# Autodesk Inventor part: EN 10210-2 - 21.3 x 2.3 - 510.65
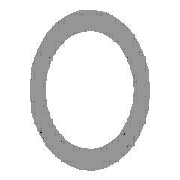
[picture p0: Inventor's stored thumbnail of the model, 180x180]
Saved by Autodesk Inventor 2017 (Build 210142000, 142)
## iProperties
Created: 2017-11
Part Number: EN 10210-2 - 21.3 x 2.3 - 510.65
Material: Steel, Mild
Description: Pipe
Document SubType Name: Modeling
Standard: DIN
Designer: iusti
Standard Revision: 2006-07
Standards Organization: DIN
Language: en-US
Size Designation: 21.3 x 2.3
Categories: <MemberInstance><Categories><Category DisplayName="Structural Shapes" InternalName="089c4875-fa83-4c05-b084-43b9cc11f5ed" Mnemonic="GRDR"><CategoryParameter Dis
Stock Number: 21.3 x 2.3
Density: 7.85 g/cm^3
Appearance: Semi-Polished
_CCFamilyMember: 1
_CCFamilyDisplayName: DIN EN 10210-2 - Pipe
_FrameMemberDoc: Frame Member File
_Version: 15.0.0
_GetPNFromCC: 1
G_L: 510.650 mm
G_W: 21.300 mm
G_H: 21.300 mm
+22488682-7980-44F7-8CC4-272C3B725D64+CUTDETAIL1: Miter 45.00 deg
IsCustomPart: 1
Author: iusti
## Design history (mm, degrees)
node "Start plane"
node "End plane"
sketch "Sketch"
  geometry: C1 r 8.35 at (0, 0); C2 r 10.65 at (0, 0); 2 further points
  constraints: 3 coincident, 2 centre point
  dimensions: "d0" = 21.3 diameter of C2 (= G_H); "d1" = 2.3 radial gap between concentric circles of C2 C1 (= G_T)
extrude "Body" new body sketch "Sketch" stored distance "d2" = 510.65 (= G_L); taper "d3" = 0 deg
node "Driven Length"
  sketch "Sketch3"
    geometry: L1 (0, 0)-(10, 0) reference
    constraints: 2 end point, 1 horizontal
  workplane "Work Plane3"
  sketch "Sketch4"
    geometry: L1 (-2, 0)-(12, 0) reference; L2 (-2, 510.65)-(12, 510.65) reference
    dimensions: "d7" = 510.65 distance between parallel lines of L1 L2 (derived)
workplane "Work Plane4"
split "Split1"
body "Solid1"
other parameters: "G_H" = 21.3 [user parameter; used in 1 equation term], "G_T" = 2.3 [user parameter; used in 1 equation term], "G_L" = 510.65 (= d7) [user parameter; used in 1 equation term], "G_OFFSET_START" = 0 [user parameter; used in 1 equation term], "G_OFFSET_END" = 10.65 [user parameter; used in 1 equation term], "d4" = 0 (computed from G_OFFSET_START), "d5" = 510.65 (= G_OFFSET_END + B_L), "d6" = 90 deg
